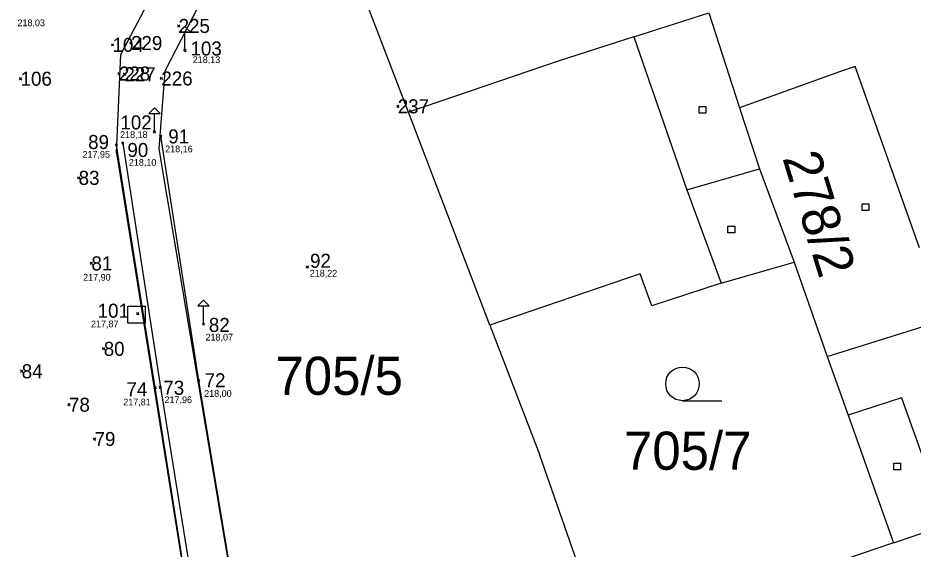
# Model space of a CAD drawing. Extents: x -711879 to -711361, y -1048782 to -1048177.
# Drawn here: x -711645.08 to -711605.14, y -1048569.9 to -1048546.23 of the extents above; entities that cross this region are included whole.
import ezdxf

# ---------------------------------------------------------------- set-up
doc = ezdxf.new("R2010")
doc.units = 0
for name, color, linetype in [('body', 7, 'Continuous'), ('kresba', 7, 'Continuous'), ('Vrstva 1', 7, 'Continuous'), ('Vrstva 14', 7, 'Continuous'), ('Vrstva 15', 7, 'Continuous'), ('Vrstva 2', 7, 'Continuous'), ('Vrstva 20', 7, 'Continuous'), ('Vrstva 23', 7, 'Continuous'), ('Vrstva 25', 7, 'Continuous'), ('Vrstva 41', 7, 'Continuous'), ('výšky', 7, 'Continuous')]:
    doc.layers.add(name, color=color, linetype=linetype)

msp = doc.modelspace()

# ---------------------------------------------------------------- linework, layer by layer
at = {"layer": 'kresba'}
for points in [[(-711637.63, -1048547.68), (-711637.63, -1048546.86), (-711637.38, -1048546.86), (-711637.63, -1048546.61), (-711637.88, -1048546.86), (-711637.63, -1048546.86)], [(-711638.99, -1048551.31), (-711638.99, -1048550.49), (-711638.74, -1048550.49), (-711638.99, -1048550.24), (-711639.24, -1048550.49), (-711638.99, -1048550.49)], [(-711633.18, -1048586.06), (-711635.31, -1048572.55), (-711637.01, -1048562.39), (-711638.71, -1048551.5)], [(-711627.73, -1048627.29), (-711630.24, -1048616.57), (-711631.79, -1048607.69), (-711633.85, -1048594.65), (-711635.19, -1048586.31), (-711637.32, -1048573.04), (-711638.96, -1048562.71), (-711640.68, -1048551.9)], [(-711640.4, -1048551.81), (-711638.72, -1048562.7), (-711637.06, -1048572.96), (-711634.96, -1048586.24)], [(-711636.8, -1048559.88), (-711636.8, -1048559.06), (-711636.55, -1048559.06), (-711636.8, -1048558.81), (-711637.05, -1048559.06), (-711636.8, -1048559.06)]]:
    msp.add_lwpolyline(points, dxfattribs=at)
msp.add_lwpolyline([(-711640.175, -1048559.08), (-711639.405, -1048559.08), (-711639.405, -1048559.84), (-711640.175, -1048559.84)], close=True, dxfattribs=at)
at = {"layer": 'Vrstva 1'}
for p, q in [((-711627.66, -1048550.43), (-711631.11, -1048541.42)), ((-711640.49, -1048547.86), (-711637.91, -1048542.94)), ((-711636.23, -1048544.16), (-711638.53, -1048548.61)), ((-711614.25, -1048546.01), (-711612.88, -1048550.24)), ((-711640.68, -1048552.25), (-711640.49, -1048547.86)), ((-711607.73, -1048548.39), (-711608.42, -1048548.64)), ((-711604.86, -1048556.48), (-711607.73, -1048548.39)), ((-711638.53, -1048548.61), (-711638.79, -1048552.06)), ((-711608.42, -1048548.64), (-711612.88, -1048550.24)), ((-711624.02, -1048559.92), (-711627.66, -1048550.43)), ((-711612.88, -1048550.24), (-711612, -1048552.95)), ((-711638.79, -1048552.06), (-711634.35, -1048578.5)), ((-711640.68, -1048552.25), (-711617.59, -1048696.39)), ((-711612, -1048552.95), (-711610.45, -1048557.12)), ((-711613.71, -1048558.05), (-711610.45, -1048557.12)), ((-711610.45, -1048557.12), (-711608.97, -1048561.32)), ((-711617.32, -1048557.64), (-711624.02, -1048559.92)), ((-711616.8, -1048559.07), (-711617.32, -1048557.64)), ((-711613.71, -1048558.05), (-711616.8, -1048559.07)), ((-711608.97, -1048561.32), (-711603.85, -1048559.72)), ((-711624.02, -1048559.92), (-711621.79, -1048565.72)), ((-711608.97, -1048561.32), (-711608.04, -1048563.94)), ((-711608.04, -1048563.94), (-711606.02, -1048569.63)), ((-711618.94, -1048573.9), (-711621.79, -1048565.72)), ((-711606.02, -1048569.63), (-711603.64, -1048568.82)), ((-711606.02, -1048569.63), (-711612.81, -1048571.92))]:
    msp.add_line(p, q, dxfattribs=at)
at = {"layer": 'Vrstva 2'}
for p, q in [((-711617.6, -1048547.07), (-711614.25, -1048546.01)), ((-711617.6, -1048547.07), (-711620.93, -1048548.15)), ((-711617.6, -1048547.07), (-711615.23, -1048553.89)), ((-711620.93, -1048548.15), (-711627.66, -1048550.43)), ((-711615.23, -1048553.89), (-711612, -1048552.95)), ((-711615.23, -1048553.89), (-711613.71, -1048558.05)), ((-711605.66, -1048563.17), (-711608.04, -1048563.94)), ((-711605.66, -1048563.17), (-711603.64, -1048568.82))]:
    msp.add_line(p, q, dxfattribs=at)
at = {"layer": 'Vrstva 20'}
for p, q in [((-711637.91, -1048546.59), (-711637.96, -1048546.54)), ((-711637.91, -1048546.59), (-711637.96, -1048546.64)), ((-711637.91, -1048546.59), (-711637.86, -1048546.54)), ((-711637.91, -1048546.59), (-711637.86, -1048546.64)), ((-711640.86, -1048547.43), (-711640.91, -1048547.38)), ((-711640.86, -1048547.43), (-711640.81, -1048547.38)), ((-711640.03, -1048547.35), (-711640.08, -1048547.3)), ((-711640.03, -1048547.35), (-711640.08, -1048547.4)), ((-711640.03, -1048547.35), (-711639.98, -1048547.3)), ((-711640.03, -1048547.35), (-711639.98, -1048547.4)), ((-711640.86, -1048547.43), (-711640.91, -1048547.48)), ((-711640.86, -1048547.43), (-711640.81, -1048547.48)), ((-711637.63, -1048547.68), (-711637.68, -1048547.63)), ((-711637.63, -1048547.68), (-711637.68, -1048547.73)), ((-711637.63, -1048547.68), (-711637.58, -1048547.63)), ((-711637.63, -1048547.68), (-711637.58, -1048547.73)), ((-711644.96, -1048548.94), (-711645.01, -1048548.89)), ((-711644.96, -1048548.94), (-711645.01, -1048548.99)), ((-711644.96, -1048548.94), (-711644.91, -1048548.89)), ((-711644.96, -1048548.94), (-711644.91, -1048548.99)), ((-711640.57, -1048548.71), (-711640.62, -1048548.66)), ((-711640.57, -1048548.71), (-711640.62, -1048548.76)), ((-711640.57, -1048548.71), (-711640.52, -1048548.66)), ((-711640.57, -1048548.71), (-711640.52, -1048548.76)), ((-711640.33, -1048548.74), (-711640.38, -1048548.69)), ((-711640.33, -1048548.74), (-711640.38, -1048548.79)), ((-711640.33, -1048548.74), (-711640.28, -1048548.69)), ((-711640.33, -1048548.74), (-711640.28, -1048548.79)), ((-711638.68, -1048548.93), (-711638.73, -1048548.88)), ((-711638.68, -1048548.93), (-711638.73, -1048548.98)), ((-711638.68, -1048548.93), (-711638.63, -1048548.88)), ((-711638.68, -1048548.93), (-711638.63, -1048548.98)), ((-711628.13, -1048550.17), (-711628.18, -1048550.12)), ((-711628.13, -1048550.17), (-711628.18, -1048550.22)), ((-711628.13, -1048550.17), (-711628.08, -1048550.12)), ((-711628.13, -1048550.17), (-711628.08, -1048550.22)), ((-711638.99, -1048551.31), (-711639.04, -1048551.26)), ((-711638.99, -1048551.31), (-711639.04, -1048551.36)), ((-711638.99, -1048551.31), (-711638.94, -1048551.26)), ((-711638.99, -1048551.31), (-711638.94, -1048551.36)), ((-711640.4, -1048551.81), (-711640.45, -1048551.76)), ((-711640.4, -1048551.81), (-711640.35, -1048551.76)), ((-711638.71, -1048551.5), (-711638.76, -1048551.45)), ((-711638.71, -1048551.5), (-711638.76, -1048551.55)), ((-711638.71, -1048551.5), (-711638.66, -1048551.45)), ((-711638.71, -1048551.5), (-711638.66, -1048551.55)), ((-711640.68, -1048551.9), (-711640.73, -1048551.85)), ((-711640.68, -1048551.9), (-711640.73, -1048551.95)), ((-711640.68, -1048551.9), (-711640.63, -1048551.85)), ((-711640.68, -1048551.9), (-711640.63, -1048551.95)), ((-711640.4, -1048551.81), (-711640.45, -1048551.86)), ((-711640.4, -1048551.81), (-711640.35, -1048551.86)), ((-711642.37, -1048553.36), (-711642.42, -1048553.31)), ((-711642.37, -1048553.36), (-711642.42, -1048553.41)), ((-711642.37, -1048553.36), (-711642.32, -1048553.31)), ((-711642.37, -1048553.36), (-711642.32, -1048553.41)), ((-711641.8, -1048557.17), (-711641.85, -1048557.12)), ((-711641.8, -1048557.17), (-711641.85, -1048557.22)), ((-711641.8, -1048557.17), (-711641.75, -1048557.12)), ((-711641.8, -1048557.17), (-711641.75, -1048557.22)), ((-711632.17, -1048557.33), (-711632.22, -1048557.28)), ((-711632.17, -1048557.33), (-711632.22, -1048557.38)), ((-711632.17, -1048557.33), (-711632.12, -1048557.28)), ((-711632.17, -1048557.33), (-711632.12, -1048557.38)), ((-711639.74, -1048559.41), (-711639.79, -1048559.36)), ((-711639.74, -1048559.41), (-711639.69, -1048559.36)), ((-711639.74, -1048559.41), (-711639.79, -1048559.46)), ((-711639.74, -1048559.41), (-711639.69, -1048559.46)), ((-711636.8, -1048559.88), (-711636.85, -1048559.83)), ((-711636.8, -1048559.88), (-711636.85, -1048559.93)), ((-711636.8, -1048559.88), (-711636.75, -1048559.83)), ((-711636.8, -1048559.88), (-711636.75, -1048559.93)), ((-711641.25, -1048560.98), (-711641.3, -1048560.93)), ((-711641.25, -1048560.98), (-711641.2, -1048560.93)), ((-711641.25, -1048560.98), (-711641.3, -1048561.03)), ((-711641.25, -1048560.98), (-711641.2, -1048561.03)), ((-711644.91, -1048561.98), (-711644.96, -1048561.93)), ((-711644.91, -1048561.98), (-711644.96, -1048562.03)), ((-711644.91, -1048561.98), (-711644.86, -1048561.93)), ((-711644.91, -1048561.98), (-711644.86, -1048562.03)), ((-711637.01, -1048562.39), (-711637.06, -1048562.34)), ((-711637.01, -1048562.39), (-711637.06, -1048562.44)), ((-711637.01, -1048562.39), (-711636.96, -1048562.34)), ((-711637.01, -1048562.39), (-711636.96, -1048562.44)), ((-711638.96, -1048562.71), (-711639.01, -1048562.66)), ((-711638.96, -1048562.71), (-711639.01, -1048562.76)), ((-711638.96, -1048562.71), (-711638.91, -1048562.66)), ((-711638.96, -1048562.71), (-711638.91, -1048562.76)), ((-711638.72, -1048562.7), (-711638.77, -1048562.65)), ((-711638.72, -1048562.7), (-711638.77, -1048562.75)), ((-711638.72, -1048562.7), (-711638.67, -1048562.65)), ((-711638.72, -1048562.7), (-711638.67, -1048562.75)), ((-711642.8, -1048563.47), (-711642.85, -1048563.42)), ((-711642.8, -1048563.47), (-711642.85, -1048563.52)), ((-711642.8, -1048563.47), (-711642.75, -1048563.42)), ((-711642.8, -1048563.47), (-711642.75, -1048563.52)), ((-711641.66, -1048565), (-711641.71, -1048564.95)), ((-711641.66, -1048565), (-711641.61, -1048564.95)), ((-711641.66, -1048565), (-711641.71, -1048565.05)), ((-711641.66, -1048565), (-711641.61, -1048565.05))]:
    msp.add_line(p, q, dxfattribs=at)
at = {"layer": 'Vrstva 23'}
msp.add_line((-711615.43, -1048563.29), (-711613.68, -1048563.29), dxfattribs=at)
msp.add_circle((-711615.43, -1048562.54), 0.75, dxfattribs=at)
at = {"layer": 'Vrstva 25'}
for p, q in [((-711614.69, -1048550.18), (-711614.39, -1048550.18)), ((-711614.69, -1048550.48), (-711614.69, -1048550.18)), ((-711614.39, -1048550.18), (-711614.39, -1048550.48)), ((-711614.39, -1048550.48), (-711614.69, -1048550.48)), ((-711607.41, -1048554.52), (-711607.11, -1048554.52)), ((-711607.41, -1048554.82), (-711607.41, -1048554.52)), ((-711607.11, -1048554.52), (-711607.11, -1048554.82)), ((-711607.11, -1048554.82), (-711607.41, -1048554.82)), ((-711613.4, -1048555.51), (-711613.1, -1048555.51)), ((-711613.4, -1048555.81), (-711613.4, -1048555.51)), ((-711613.1, -1048555.51), (-711613.1, -1048555.81)), ((-711613.1, -1048555.81), (-711613.4, -1048555.81)), ((-711606, -1048566.07), (-711605.7, -1048566.07)), ((-711606, -1048566.37), (-711606, -1048566.07)), ((-711605.7, -1048566.07), (-711605.7, -1048566.37)), ((-711605.7, -1048566.37), (-711606, -1048566.37))]:
    msp.add_line(p, q, dxfattribs=at)
at = {"layer": 'Vrstva 41'}
for p, q in [((-711637.91, -1048546.59), (-711637.91, -1048546.59)), ((-711640.03, -1048547.35), (-711640.03, -1048547.35)), ((-711640.86, -1048547.43), (-711640.86, -1048547.43)), ((-711637.63, -1048547.68), (-711637.63, -1048547.68)), ((-711644.96, -1048548.94), (-711644.96, -1048548.94)), ((-711640.57, -1048548.71), (-711640.57, -1048548.71)), ((-711640.33, -1048548.74), (-711640.33, -1048548.74)), ((-711638.68, -1048548.93), (-711638.68, -1048548.93)), ((-711628.13, -1048550.17), (-711628.13, -1048550.17)), ((-711638.99, -1048551.31), (-711638.99, -1048551.31)), ((-711638.71, -1048551.5), (-711638.71, -1048551.5)), ((-711640.68, -1048551.9), (-711640.68, -1048551.9)), ((-711640.4, -1048551.81), (-711640.4, -1048551.81)), ((-711642.37, -1048553.36), (-711642.37, -1048553.36)), ((-711641.8, -1048557.17), (-711641.8, -1048557.17)), ((-711632.17, -1048557.33), (-711632.17, -1048557.33)), ((-711639.74, -1048559.41), (-711639.74, -1048559.41)), ((-711636.8, -1048559.88), (-711636.8, -1048559.88)), ((-711641.25, -1048560.98), (-711641.25, -1048560.98)), ((-711644.91, -1048561.98), (-711644.91, -1048561.98)), ((-711637.01, -1048562.39), (-711637.01, -1048562.39)), ((-711638.96, -1048562.71), (-711638.96, -1048562.71)), ((-711638.72, -1048562.7), (-711638.72, -1048562.7)), ((-711642.8, -1048563.47), (-711642.8, -1048563.47)), ((-711641.66, -1048565), (-711641.66, -1048565))]:
    msp.add_line(p, q, dxfattribs=at)

# ---------------------------------------------------------------- texts
at = {"layer": 'body'}
for s, p in [('225', (-711637.91, -1048546.902)), ('104', (-711640.86, -1048547.743)), ('229', (-711640.03, -1048547.662)), ('103', (-711637.379, -1048547.905)), ('228', (-711640.57, -1048549.023)), ('227', (-711640.33, -1048549.052)), ('106', (-711644.96, -1048549.253)), ('226', (-711638.68, -1048549.243)), ('237', (-711628.13, -1048550.483)), ('102', (-711640.506, -1048551.201)), ('91', (-711638.37, -1048551.824)), ('89', (-711641.945, -1048552.074)), ('90', (-711640.194, -1048552.43)), ('83', (-711642.37, -1048553.672)), ('81', (-711641.8, -1048557.483)), ('92', (-711632.046, -1048557.368)), ('101', (-711641.522, -1048559.592)), ('82', (-711636.56, -1048560.226)), ('80', (-711641.25, -1048561.292)), ('84', (-711644.91, -1048562.292)), ('72', (-711636.75, -1048562.694)), ('74', (-711640.237, -1048563.094)), ('73', (-711638.591, -1048563.026)), ('78', (-711642.8, -1048563.782)), ('79', (-711641.66, -1048565.312))]:
    msp.add_text(s, height=0.625, dxfattribs=at).set_placement(p)
at = {"layer": 'Vrstva 14'}
for s, p in [('705/5', (-711633.59, -1048563.03)), ('705/7', (-711618.04, -1048566.37))]:
    msp.add_text(s, height=1.7, dxfattribs=at).set_placement(p)
at = {"layer": 'Vrstva 15'}
msp.add_text('278/2', height=1.7, rotation=287.1841, dxfattribs=at).set_placement((-711610.98, -1048552.47))
at = {"layer": 'výšky'}
for s, p in [('218,03', (-711645.1, -1048546.6)), ('218,13', (-711637.28, -1048548.24)), ('218,18', (-711640.52, -1048551.58)), ('217,95', (-711642.2, -1048552.46)), ('218,16', (-711638.51, -1048552.22)), ('218,10', (-711640.13, -1048552.82)), ('217,90', (-711642.17, -1048557.94)), ('218,22', (-711632.06, -1048557.76)), ('217,87', (-711641.82, -1048560.02)), ('218,07', (-711636.71, -1048560.61)), ('218,00', (-711636.77, -1048563.12)), ('217,81', (-711640.38, -1048563.5)), ('217,96', (-711638.54, -1048563.4))]:
    msp.add_text(s, height=0.3, dxfattribs=at).set_placement(p)

doc.saveas('drawing.dxf')
